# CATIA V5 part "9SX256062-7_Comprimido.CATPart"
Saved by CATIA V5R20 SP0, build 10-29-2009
Part number: 9SX256062-7_Comprimido
Revision: ANY
Definition: UNKNOWN
Nomenclature: 9SX256062-7_Comprimido
Source: Unknown
Bounding box of the stored display mesh (mm): x -21.1 to 21.1, y -1.25 to 14.75, z -21.1 to 21.1
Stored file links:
  C:\Users\Utente\Desktop\IO LAVORO\3D X SITO CF\CUMSA\3D files SX.256062\SX 256062\9SX256062-7_Comprimido.CATPart
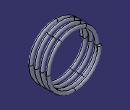
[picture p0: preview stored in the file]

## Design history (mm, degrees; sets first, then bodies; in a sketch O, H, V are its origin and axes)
Body1 "Revolución2" (main body)
  Solid1: solid without history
